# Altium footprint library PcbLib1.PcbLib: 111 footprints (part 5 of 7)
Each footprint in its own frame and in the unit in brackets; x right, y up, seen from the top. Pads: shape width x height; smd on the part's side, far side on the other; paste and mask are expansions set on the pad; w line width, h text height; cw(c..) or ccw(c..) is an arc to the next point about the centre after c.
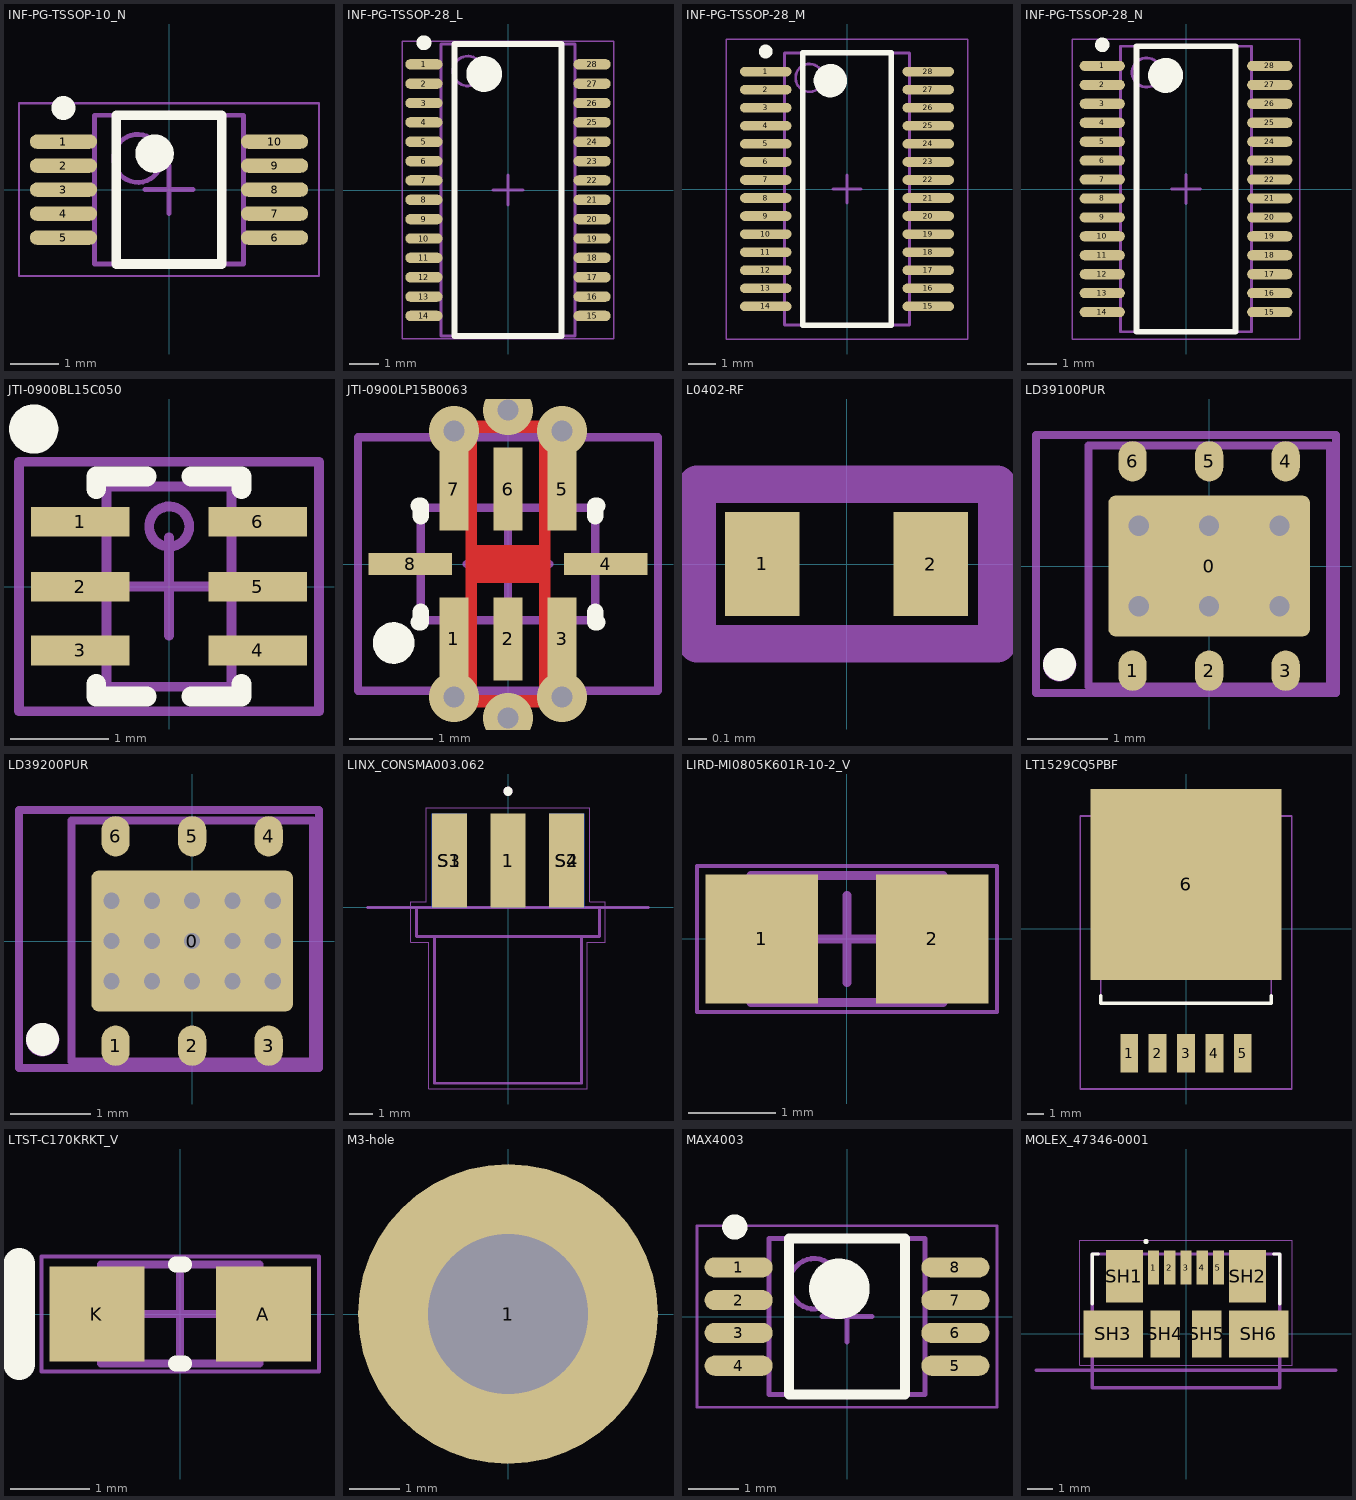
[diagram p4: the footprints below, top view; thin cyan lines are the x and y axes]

## INF-PG-TSSOP-10_N [mm] "SOP, 10-Leads, Body 3x3 mm, Pitch 0.5 mm, IPC Medium Density"
height 1.05
pads (10):
  oval 1.4x0.3 smd: 1(-2.2,1) 2(-2.2,0.5) 3(-2.2,0) 4(-2.2,-0.5) 5(-2.2,-1) 6(2.2,-1) 7(2.2,-0.5) 8(2.2,0) 9(2.2,0.5) 10(2.2,1)
Top Overlay:
  circle w0.4: c-0.3,0.75 r0.2
  circle w0.25: c-2.2,1.7 r0.125
  lines w0.2: -1.1,-1.55 1.1,-1.55 1.1,1.55 -1.1,1.55 -1.1,-1.55
Mechanical 13:
  circle w0.1: c-0.65,0.65 r0.5
  lines w0.1: -1.55,-1.55 1.55,-1.55 1.55,1.55 -1.55,1.55 -1.55,-1.55
Mechanical 15:
  lines w0.05: -3.125,-1.8 3.125,-1.8 3.125,1.8 -3.125,1.8 -3.125,-1.8
  lines w0.1: -0.5,0 0.5,0 ; 0,-0.5 0,0.5
3D body: height 1.05, standoff 0.1, extent -1.55,-1.55 1.55,1.55

## INF-PG-TSSOP-28_L [mm] "SOP, 28-Leads, Body 9.7x4.4 mm, Pitch 0.65 mm, IPC High Density"
height 1.2
pads (28):
  oval 1.25x0.35 smd: 1(-2.825,4.225) 2(-2.825,3.575) 3(-2.825,2.925) 4(-2.825,2.275) 5(-2.825,1.625) 6(-2.825,0.975) 7(-2.825,0.325) 8(-2.825,-0.325) 9(-2.825,-0.975) 10(-2.825,-1.625) 11(-2.825,-2.275) 12(-2.825,-2.925) 13(-2.825,-3.575) 14(-2.825,-4.225) 15(2.825,-4.225) 16(2.825,-3.575) 17(2.825,-2.925) 18(2.825,-2.275) 19(2.825,-1.625) 20(2.825,-0.975) 21(2.825,-0.325) 22(2.825,0.325) 23(2.825,0.975) 24(2.825,1.625) 25(2.825,2.275) 26(2.825,2.925) 27(2.825,3.575) 28(2.825,4.225)
Top Overlay:
  circle w0.25: c-2.825,4.95 r0.125
  circle w0.6: c-0.8,3.9 r0.3
  lines w0.2: -1.8,-4.9 -1.8,4.9 1.8,4.9 1.8,-4.9 -1.8,-4.9
Mechanical 13:
  circle w0.1: c-1.35,4 r0.5
  lines w0.1: -2.25,-4.9 -2.25,4.9 2.25,4.9 2.25,-4.9 -2.25,-4.9
Mechanical 15:
  lines w0.05: -3.55,-5 -3.55,5 3.55,5 3.55,-5 -3.55,-5
  lines w0.1: -0.5,0 0.5,0 ; 0,-0.5 0,0.5
3D body: height 1.2, standoff 0.05, extent -2.25,-4.9 2.25,4.9

## INF-PG-TSSOP-28_M [mm] "SOP, 28-Leads, Body 9.7x4.4 mm, Pitch 0.65 mm, IPC Low Density"
height 1.2
pads (28):
  oval 1.85x0.35 smd: 1(-2.925,4.225) 2(-2.925,3.575) 3(-2.925,2.925) 4(-2.925,2.275) 5(-2.925,1.625) 6(-2.925,0.975) 7(-2.925,0.325) 8(-2.925,-0.325) 9(-2.925,-0.975) 10(-2.925,-1.625) 11(-2.925,-2.275) 12(-2.925,-2.925) 13(-2.925,-3.575) 14(-2.925,-4.225) 15(2.925,-4.225) 16(2.925,-3.575) 17(2.925,-2.925) 18(2.925,-2.275) 19(2.925,-1.625) 20(2.925,-0.975) 21(2.925,-0.325) 22(2.925,0.325) 23(2.925,0.975) 24(2.925,1.625) 25(2.925,2.275) 26(2.925,2.925) 27(2.925,3.575) 28(2.925,4.225)
Top Overlay:
  circle w0.25: c-2.925,4.95 r0.125
  circle w0.6: c-0.6,3.9 r0.3
  lines w0.2: -1.6,-4.9 -1.6,4.9 1.6,4.9 1.6,-4.9 -1.6,-4.9
Mechanical 13:
  circle w0.1: c-1.35,4 r0.5
  lines w0.1: -2.25,-4.9 -2.25,4.9 2.25,4.9 2.25,-4.9 -2.25,-4.9
Mechanical 15:
  lines w0.05: -4.35,-5.4 -4.35,5.4 4.35,5.4 4.35,-5.4 -4.35,-5.4
  lines w0.1: -0.5,0 0.5,0 ; 0,-0.5 0,0.5
3D body: height 1.2, standoff 0.05, extent -2.25,-4.9 2.25,4.9

## INF-PG-TSSOP-28_N [mm] "SOP, 28-Leads, Body 9.7x4.4 mm, Pitch 0.65 mm, IPC Medium Density"
height 1.2
pads (28):
  oval 1.55x0.35 smd: 1(-2.875,4.225) 2(-2.875,3.575) 3(-2.875,2.925) 4(-2.875,2.275) 5(-2.875,1.625) 6(-2.875,0.975) 7(-2.875,0.325) 8(-2.875,-0.325) 9(-2.875,-0.975) 10(-2.875,-1.625) 11(-2.875,-2.275) 12(-2.875,-2.925) 13(-2.875,-3.575) 14(-2.875,-4.225) 15(2.875,-4.225) 16(2.875,-3.575) 17(2.875,-2.925) 18(2.875,-2.275) 19(2.875,-1.625) 20(2.875,-0.975) 21(2.875,-0.325) 22(2.875,0.325) 23(2.875,0.975) 24(2.875,1.625) 25(2.875,2.275) 26(2.875,2.925) 27(2.875,3.575) 28(2.875,4.225)
Top Overlay:
  circle w0.25: c-2.875,4.95 r0.125
  circle w0.6: c-0.7,3.9 r0.3
  lines w0.2: -1.7,-4.9 -1.7,4.9 1.7,4.9 1.7,-4.9 -1.7,-4.9
Mechanical 13:
  circle w0.1: c-1.35,4 r0.5
  lines w0.1: -2.25,-4.9 -2.25,4.9 2.25,4.9 2.25,-4.9 -2.25,-4.9
Mechanical 15:
  lines w0.05: -3.9,-5.15 -3.9,5.15 3.9,5.15 3.9,-5.15 -3.9,-5.15
  lines w0.1: -0.5,0 0.5,0 ; 0,-0.5 0,0.5
3D body: height 1.2, standoff 0.05, extent -2.25,-4.9 2.25,4.9

## JTI-0900BL15C050 [mm] "900 MHz Balun 1:1"
height 0.95
pads (6):
  rect 1x0.3 smd mask+0.07: 1(-0.9,0.66) 2(-0.9,0) 3(-0.9,-0.65) 4(0.9,-0.65) 5(0.9,0) 6(0.9,0.66)
Top Overlay:
  circle w0.25: c-1.375,1.6 r0.125
  lines w0.2: -0.739,-0.99 -0.739,-1.118 -0.225,-1.118 ; -0.739,0.99 -0.739,1.118 -0.225,1.118 ; 0.225,-1.118 0.737,-1.118 0.737,-0.99 ; 0.225,1.118 0.737,1.118 0.737,0.99
Mechanical 13:
  circle w0.1: c0.002,0.61 r0.204
  lines w0.1: -0.635,-1.019 0.635,-1.019 0.635,1.016 -0.635,1.016 -0.635,-1.019
Mechanical 15:
  lines w0.1: -0.5,0 0.5,0 ; 0,-0.5 0,0.5 ; -1.524,-1.267 1.524,-1.267 1.524,1.267 -1.524,1.267 -1.524,-1.267
3D body: height 0.86, standoff 0, extent -0.641,0.508 -0.324,0.813
3D body: height 0.86, standoff 0, extent -0.641,-0.15 -0.324,0.155
3D body: height 0.86, standoff 0, extent -0.641,-0.8 -0.324,-0.495
3D body: height 0.86, standoff 0, extent 0.33,-0.8 0.648,-0.495
3D body: height 0.86, standoff 0, extent 0.321,0.511 0.639,0.815
3D body: height 0.85, standoff 0, extent -0.635,-1.016 0.635,1.016
3D body: height 0.86, standoff 0, extent 0.324,-0.152 0.641,0.152
3D body: height 0.86, standoff 0, extent -0.229,0.464 0.229,0.755

## JTI-0900LP15B0063 [mm] "900 MHz Low Pass Filter"
height 1.05
pads (8):
  rect 0.35x1 smd mask+0.05: 1(-0.65,-0.9) 2(0,-0.9) 3(0.65,-0.9) 5(0.65,0.9) 6(0,0.9) 7(-0.65,0.9)
  rect 1x0.27 smd mask+0.05: 4(1.175,0) 8(-1.175,0)
via -0.65,1.6 diameter 0.6 hole 0.25
via 0,1.85 diameter 0.6 hole 0.25
via 0.65,1.6 diameter 0.6 hole 0.25
via -0.65,-1.6 diameter 0.6 hole 0.25
via 0.65,-1.6 diameter 0.6 hole 0.25
via 0,-1.85 diameter 0.6 hole 0.25
Top Layer:
  region: -0.511,-0.399 -0.511,1.4 -0.375,1.4 -0.375,0.225 0,0.225 0,-0.225 -0.375,-0.225 -0.375,-1.4 -0.511,-1.4
  region: 0.51,0.399 0.51,-1.4 0.375,-1.4 0.375,-0.225 0,-0.225 0,0.225 0.375,0.225 0.375,1.4 0.51,1.4
  region: -0.375,1.4 -0.375,1.575 0.375,1.575 0.375,1.4 0.51,1.4 0.51,1.725 -0.511,1.725 -0.511,1.4
  region: 0.375,-1.4 0.375,-1.575 -0.375,-1.575 -0.375,-1.4 -0.51,-1.4 -0.51,-1.725 0.511,-1.725 0.511,-1.4
Top Overlay:
  circle w0.25: c-1.375,-0.95 r0.125
  lines w0.2: -1.075,-0.7 -1.05,-0.7 -1.05,-0.575 ; -1.075,0.7 -1.05,0.7 -1.05,0.575 ; 1.05,-0.575 1.05,-0.7 1.075,-0.7 ; 1.05,0.575 1.05,0.7 1.075,0.7
Mechanical 13:
  lines w0.1: -1.05,-0.675 1.05,-0.675 1.05,0.675 -1.05,0.675 -1.05,-0.675
Mechanical 15:
  lines w0.1: -0.5,0 0.5,0 ; 0,-0.5 0,0.5 ; -1.803,-1.524 1.803,-1.524 1.803,1.524 -1.803,1.524 -1.803,-1.524
3D body: height 0.95, standoff 0, extent -1.05,-0.675 1.05,0.675
3D body: height 0.96, standoff 0, extent -0.85,-0.7 -0.45,-0.45
3D body: height 0.96, standoff 0, extent -0.7,-0.2 -0.35,0.2
3D body: height 0.96, standoff 0, extent -0.2,-0.7 0.2,-0.45
3D body: height 0.96, standoff 0, extent 0.45,-0.7 0.85,-0.45
3D body: height 0.96, standoff 0, extent 0.45,0.45 0.85,0.7
3D body: height 0.96, standoff 0, extent -0.2,0.45 0.2,0.7
3D body: height 0.96, standoff 0, extent -0.85,0.45 -0.45,0.7
3D body: height 0.96, standoff 0, extent -1.075,-0.2 -0.825,0.2
3D body: height 0.96, standoff 0, extent 0.825,-0.2 1.075,0.2

## L0402-RF [mm]
height 1
pads (2):
  rect 0.4x0.559 smd paste+0 mask+0: 1(-0.454,0) 2(0.454,0)
Mechanical 13:
  lines w0.203: -0.805,-0.43 -0.805,0.43 0.81,0.43 0.81,-0.43 -0.805,-0.43
3D body: height 0.31, standoff 0, extent -0.55,-0.275 -0.275,0.275
3D body: height 0.3, standoff 0, extent -0.533,-0.27 0.533,0.27
3D body: height 0.31, standoff 0, extent 0.275,-0.275 0.55,0.275

## LD39100PUR [mm] "1 A, low quiescent current, low-noise voltage regulator"
height 1
pads (7):
  rrect10% 2.5x1.75 smd mask+0.05: 0(0,0)
  oval 0.35x0.5 smd mask+0.05: 1(-0.95,-1.3) 2(0,-1.3) 3(0.95,-1.3) 4(0.95,1.3) 5(0,1.3) 6(-0.95,1.3)
via 0.875,-0.5 diameter 0.6 hole 0.25
via -0.875,-0.5 diameter 0.6 hole 0.25
via 0,-0.5 diameter 0.6 hole 0.25
via 0.875,0.5 diameter 0.6 hole 0.25
via -0.875,0.5 diameter 0.6 hole 0.25
via 0,0.5 diameter 0.6 hole 0.25
Top Overlay:
  circle w0.25: c-1.858,-1.222 r0.078
Mechanical 13:
  circle w0.1: c-1.858,-1.225 r0.158
  lines w0.1: -1.499,-1.499 -1.499,1.499 1.499,1.499 1.499,-1.499 -1.499,-1.499
Mechanical 15:
  lines w0.1: -0.5,0 0.5,0 ; 0,-0.5 0,0.5 ; -2.15,-1.575 -2.15,1.625 1.575,1.625 1.575,-1.575 -2.15,-1.575
3D body "User Library-dfn6_3x3_rm0_95.STEP": height 0.75, standoff -0.05, extent -1.5,-1.55 1.5,1.55

## LD39200PUR [mm] "2 A, low quiescent current, low-noise voltage regulator"
height 1
pads (7):
  rrect10% 2.5x1.75 smd mask+0.05: 0(0,0)
  oval 0.35x0.5 smd mask+0.05: 1(-0.95,-1.3) 2(0,-1.3) 3(0.95,-1.3) 4(0.95,1.3) 5(0,1.3) 6(-0.95,1.3)
via -0.5,-0.5 diameter 0.4 hole 0.2
via -1,-0.5 diameter 0.4 hole 0.2
via -0.5,0.5 diameter 0.4 hole 0.2
via -1,0.5 diameter 0.4 hole 0.2
via -1,0 diameter 0.4 hole 0.2
via -0.5,0 diameter 0.4 hole 0.2
via 1,0.5 diameter 0.4 hole 0.2
via 1,0 diameter 0.4 hole 0.2
via 0.5,-0.5 diameter 0.4 hole 0.2
via 1,-0.5 diameter 0.4 hole 0.2
via 0.5,0.5 diameter 0.4 hole 0.2
via 0.5,0 diameter 0.4 hole 0.2
via 0,0.5 diameter 0.4 hole 0.2
via 0,-0.5 diameter 0.4 hole 0.2
via 0,0 diameter 0.4 hole 0.2
Top Overlay:
  circle w0.25: c-1.858,-1.222 r0.078
Mechanical 13:
  circle w0.1: c-1.858,-1.225 r0.158
  lines w0.1: -1.499,-1.499 -1.499,1.499 1.499,1.499 1.499,-1.499 -1.499,-1.499
Mechanical 15:
  lines w0.1: -0.5,0 0.5,0 ; 0,-0.5 0,0.5 ; -2.15,-1.575 -2.15,1.625 1.575,1.625 1.575,-1.575 -2.15,-1.575
3D body "User Library-dfn6_3x3_rm0_95.STEP": height 0.75, standoff -0.05, extent -1.5,-1.55 1.5,1.55

## LINX_CONSMA003.062 [mm]
pads (5):
  rect 1.52x4.06 smd: 1(0,2.03) S1(-2.54,2.03) S2(2.54,2.03)
  rect 1.52x4.06 smd far side: S3(-2.54,2.03) S4(2.54,2.03)
Top Overlay:
  circle w0.2: c0,5.03 r0.1
Mechanical 13:
  circle w0.2: c0,5.03 r0.1
  lines w0.05: -4.215,-1.51 -3.425,-1.51 -3.425,-7.86 3.425,-7.86 3.425,-1.51 4.215,-1.51 4.215,0.25 3.55,0.25 3.55,4.31 -3.55,4.31 -3.55,0.25 -4.215,0.25 -4.215,-1.51
  lines w0.127: -6.09,0 -3.05,0 ; -3.965,0 -3.965,-1.26 -3.175,-1.26 ; 3.965,0 3.965,-1.26 3.175,-1.26 ; 6.09,0 3.05,0 ; -3.175,-1.26 3.175,-1.26 ; -3.175,-1.26 -3.175,-7.61 3.175,-7.61 3.175,-1.26 ; -3.05,0 -3.05,3.9 -2,3.9 -2,0 ; -3.05,0 -2,0 ; -2,0 -0.65,0 ; -0.65,0 -0.65,3.9 0.65,3.9 0.65,0 ; -0.65,0 0.65,0 ; 0.65,0 2,0 ; 2,0 2,3.9 3.05,3.9 3.05,0 ; 2,0 3.05,0
  text "PCB Edge" at 5,-0.97 h0.81
Mechanical 15:
  lines w0.05: -4.215,-1.51 -3.425,-1.51 -3.425,-7.86 3.425,-7.86 3.425,-1.51 4.215,-1.51 4.215,0.25 3.55,0.25 3.55,4.31 -3.55,4.31 -3.55,0.25 -4.215,0.25 -4.215,-1.51
3D body "CONSMA003.062--3DModel-STEP-56544.STEP": height 4.61, standoff -3.31, extent -3.993,-7.914 3.937,3.596

## LIRD-MI0805K601R-10-2_V [mm] "Chip Bead, 2-Leads, Body 2.2 x1.45 mm"
height 1.1
pads (2):
  rect 1.285x1.47 smd: 1(-0.972,0) 2(0.972,0)
Mechanical 13:
  lines w0.1: -1.1,-0.725 1.1,-0.725 1.1,0.725 -1.1,0.725 -1.1,-0.725
Mechanical 15:
  lines w0.05: -1.715,-0.835 1.715,-0.835 1.715,0.835 -1.715,0.835 -1.715,-0.835
  lines w0.1: -0.5,0 0.5,0 ; 0,-0.5 0,0.5
3D body "INDC2012X11L23.step": height 1.1, standoff 0, extent -1.1,-0.725 1.1,0.725

## LT1529CQ5PBF [mil]
pads (6):
  rect 42.01x90 smd: 1(-134.02,-292.99) 2(-67.01,-292.99) 3(0,-292.99) 4(67.01,-292.99) 5(134.02,-292.99)
  rect 450x450 smd: 6(0,105)
Top Overlay:
  lines w7.87: -201.26,-175 201.26,-175 ; -201.26,-175 201.26,-175 ; -201.26,-175 -201.26,-157.48 -201.26,-175 ; 201.26,-175 201.26,-157.48 201.26,-175
Mechanical 13:
  lines w3.94: -201.26,-175 201.26,-175 201.26,175 -201.26,175 -201.26,-175
Mechanical 15:
  lines w3.94: -249.37,-377.36 249.37,-377.36 249.37,266.38 -249.37,266.38 -249.37,-377.36
3D body "D2PAK-5.step": height 189.92, standoff 0, extent -198.97,-314.25 198.97,250.71

## LTST-C170KRKT_V [mm] "SMD, 2-Leads, Body 2x1.25mm"
height 1.2
pads (2):
  rect 1.2x1.2 smd: A(1.05,0) K(-1.05,0)
Top Overlay:
  lines w0.2: -0.051,-0.625 0.051,-0.625 ; -0.051,0.625 0.051,0.625
  lines w0.4: -2.032,-0.635 -2.032,0.635
Mechanical 13:
  lines w0.1: -0.7,-0.625 -0.7,0.625 ; 0.7,-0.625 0.7,0.625 ; -1,-0.625 1,-0.625 1,0.625 -1,0.625 -1,-0.625
Mechanical 15:
  lines w0.05: -1.75,-0.725 -1.75,0.725 1.75,0.725 1.75,-0.725 -1.75,-0.725
  lines w0.1: -0.5,0 0.5,0 ; 0,-0.5 0,0.5
3D body: height 1.2, standoff 0.5, extent -0.7,-0.625 0.7,0.625
3D body: height 0.5, standoff 0, extent -1,-0.625 1,0.625

## M3-hole [mm]
pads (1):
  round 6 hole 3.2: 1(0,0)

## MAX4003 [mm] "µmax"
height 1.1
pads (8):
  oval 1.35x0.4 smd: 1(-2.15,0.975) 2(-2.15,0.325) 3(-2.15,-0.325) 4(-2.15,-0.975) 5(2.15,-0.975) 6(2.15,-0.325) 7(2.15,0.325) 8(2.15,0.975)
Top Overlay:
  circle w0.6: c-0.15,0.55 r0.3
  circle w0.25: c-2.225,1.775 r0.125
  lines w0.2: -1.15,-1.55 1.15,-1.55 1.15,1.55 -1.15,1.55 -1.15,-1.55
Mechanical 13:
  circle w0.1: c-0.65,0.65 r0.5
  lines w0.1: -1.55,-1.55 1.55,-1.55 1.55,1.55 -1.55,1.55 -1.55,-1.55
Mechanical 15:
  lines w0.05: -2.975,-1.8 2.975,-1.8 2.975,1.8 -2.975,1.8 -2.975,-1.8
  lines w0.1: -0.5,0 0.5,0 ; 0,-0.5 0,0.5
3D body: height 1.1, standoff 0.05, extent -1.55,-1.55 1.55,1.55

## MOLEX_47346-0001 [mm]
pads (11):
  rect 0.45x1.38 smd: 1(-1.3,2.66) 2(-0.65,2.66) 3(0,2.66) 4(0.65,2.66) 5(1.3,2.66)
  rect 1.475x2.1 smd: SH1(-2.462,2.3) SH2(2.462,2.3)
  rect 2.375x1.9 smd: SH3(-2.913,0) SH6(2.913,0)
  rect 1.175x1.9 smd: SH4(-0.837,0) SH5(0.837,0)
Top Overlay:
  circle w0.1: c-1.6,3.7 r0.05
  lines w0.127: -3.75,1.2 -3.75,3.2 -3.5,3.2 ; 3.5,3.2 3.75,3.2 3.75,1.2
Mechanical 13:
  lines w0.127: -6,-1.45 6,-1.45 ; -3.75,-2.15 3.75,-2.15 3.75,3.2 -3.75,3.2 -3.75,-2.15
  text "PCB EDGE" at -5.91,-1.853 h0.31
Mechanical 15:
  lines w0.05: -4.25,-1.25 -4.25,3.75 4.25,3.75 4.25,-1.25 -4.25,-1.25
3D body "47346-0001--3DModel-STEP-56544.STEP": height 2.7, standoff -0.25, extent -4.18,-2.636 4.18,2.794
